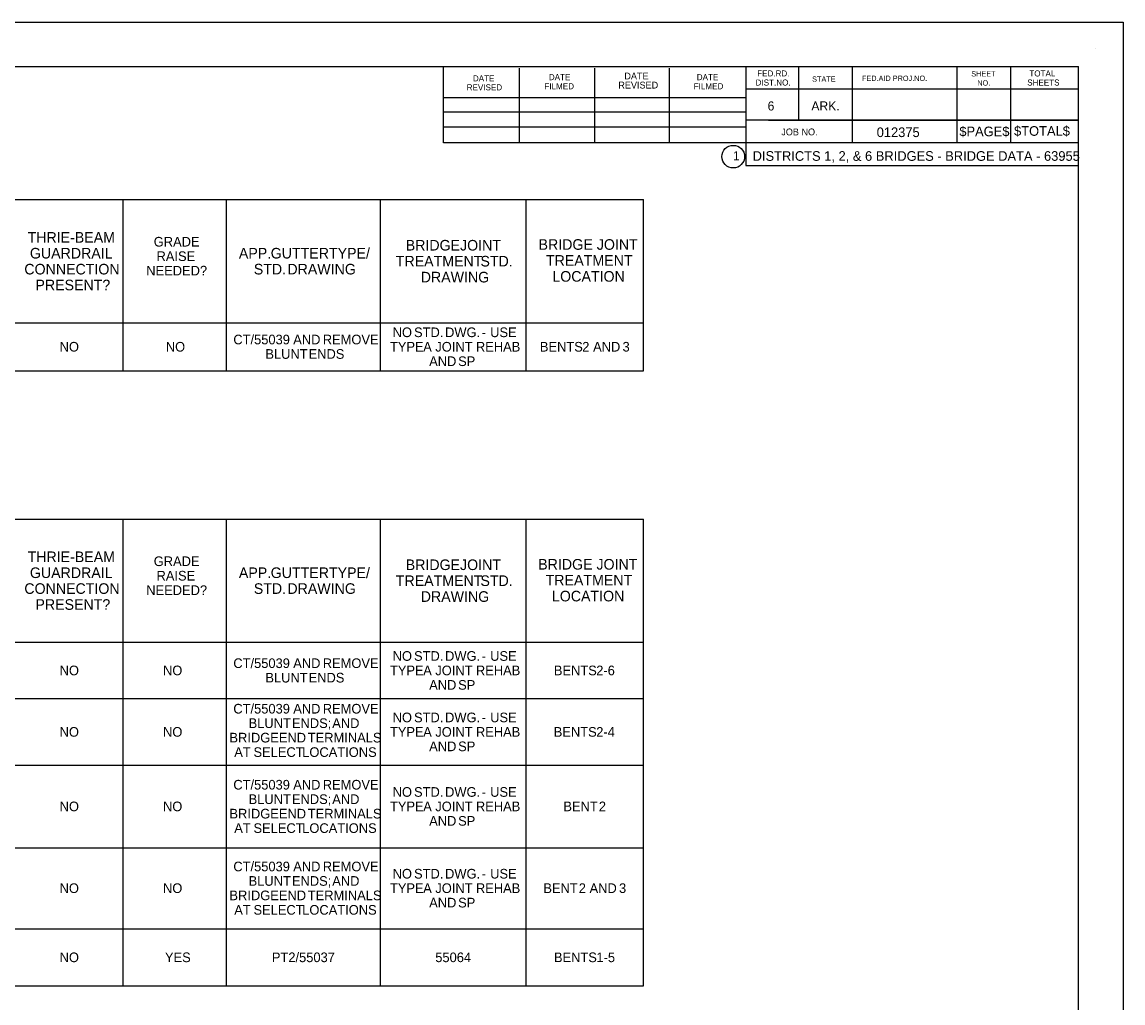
# Model space of a CAD drawing. Extents: x 16 to 1228740, y 11 to 152440.
# Drawn here: x 17.302 to 18.49, y 11.485 to 12.543 of the extents above; entities that cross this region are included whole.
import ezdxf

# ---------------------------------------------------------------- set-up
doc = ezdxf.new("R2010")
doc.units = 0
for name, color, linetype in [('B_Copy In', 7, 'Continuous'), ('B_Text', 7, 'Continuous'), ('R_Border', 7, 'Continuous')]:
    doc.layers.add(name, color=color, linetype=linetype)

msp = doc.modelspace()

# ---------------------------------------------------------------- linework, layer by layer
at = {"layer": 'B_Text'}
for p, q in [((16.2529, 12.3512), (17.9726, 12.3512)), ((17.4109, 12.1667), (17.4109, 12.3512)), ((17.5224, 12.1667), (17.5224, 12.3512)), ((17.6887, 12.1667), (17.6887, 12.3512)), ((17.8459, 12.1667), (17.8459, 12.3512)), ((17.9726, 12.1667), (17.9726, 12.3512)), ((16.2529, 12.2184), (17.9726, 12.2184)), ((16.2529, 12.2184), (17.9726, 12.2184)), ((16.2529, 12.1667), (17.9726, 12.1667)), ((16.2529, 12.0066), (17.9726, 12.0066)), ((17.4109, 11.5029), (17.4109, 12.0066)), ((17.5224, 11.5029), (17.5224, 12.0066)), ((17.6887, 11.5029), (17.6887, 12.0066)), ((17.8459, 11.5029), (17.8459, 12.0066)), ((17.9726, 11.5029), (17.9726, 12.0066)), ((16.2529, 11.8737), (17.9726, 11.8737)), ((16.2529, 11.8129), (17.9726, 11.8129)), ((16.2529, 11.7412), (17.9726, 11.7412)), ((16.2529, 11.652), (17.9726, 11.652)), ((16.2529, 11.5647), (17.9726, 11.5647)), ((16.2529, 11.5029), (17.9726, 11.5029))]:
    msp.add_line(p, q, dxfattribs=at)
at = {"layer": 'R_Border'}
for p, q in [((18.4604, 12.514), (18.4604, 12.514)), ((15.7833, 12.4948), (18.4422, 12.4948)), ((17.7567, 12.4124), (17.7567, 12.4948)), ((17.8389, 12.4124), (17.8389, 12.4931)), ((17.9202, 12.4124), (17.9202, 12.4931)), ((18.0009, 12.4124), (18.0009, 12.4931)), ((18.083, 12.4948), (18.083, 12.3881)), ((18.14, 12.4948), (18.14, 12.4369)), ((18.1979, 12.4948), (18.1979, 12.4124)), ((18.311, 12.4948), (18.311, 12.4124)), ((18.3689, 12.4948), (18.3689, 12.4124)), ((18.4422, 10.7576), (18.4422, 12.4948)), ((18.4422, 12.4703), (18.083, 12.4703)), ((18.4422, 12.4704), (18.4422, 12.4704)), ((17.7567, 12.4613), (18.083, 12.4613)), ((17.7567, 12.4458), (18.083, 12.4458)), ((18.4422, 12.4369), (18.083, 12.4369)), ((18.1077, 12.4369), (18.4422, 12.4369)), ((17.7567, 12.4124), (17.7567, 12.4296)), ((17.7567, 12.4296), (18.083, 12.4296)), ((18.4422, 12.4124), (17.7567, 12.4124)), ((18.083, 12.3881), (18.4422, 12.3881)), ((18.083, 12.3881), (18.4422, 12.3881))]:
    msp.add_line(p, q, dxfattribs=at)
msp.add_lwpolyline([(15.6569, 12.5428), (18.4903, 12.5428), (18.4903, 10.7095), (15.6569, 10.7095)], close=True, dxfattribs=at)
msp.add_circle((18.0696, 12.3976), 0.0122, dxfattribs=at)

# ---------------------------------------------------------------- texts
at = {"layer": 'B_Copy In'}
msp.add_text('DISTRICTS 1, 2, & 6 BRIDGES - BRIDGE DATA - 63955', height=0.0104, dxfattribs=at).set_placement((18.0905, 12.3931))
at = {"layer": 'B_Text'}
for s, height, p in [('THRIE-BEAM', 0.01144, (17.3078, 12.3048)), ('GRADE', 0.0104, (17.444, 12.3006)), ('BRIDGE', 0.01144, (17.716, 12.2963)), (' JOINT', 0.01144, (17.7704, 12.2963)), ('BRIDGE JOINT', 0.01144, (17.8594, 12.2971)), ('GUARDRAIL', 0.01144, (17.3103, 12.2877)), ('RAISE', 0.0104, (17.447, 12.285)), ('APP.', 0.01144, (17.5359, 12.2877)), (' GUTTER', 0.01144, (17.566, 12.2877)), (' TYPE/', 0.01144, (17.6289, 12.2877)), ('TREATMENT', 0.01144, (17.7053, 12.2791)), (' STD.', 0.01144, (17.7924, 12.2791)), ('TREATMENT', 0.01144, (17.8674, 12.2799)), ('CONNECTION', 0.01144, (17.3043, 12.2705)), ('NEEDED?', 0.0104, (17.4359, 12.2694)), ('STD.', 0.01144, (17.552, 12.2705)), (' DRAWING', 0.01144, (17.584, 12.2705)), ('DRAWING', 0.01144, (17.7322, 12.2619)), ('LOCATION', 0.01144, (17.8743, 12.2627)), ('PRESENT?', 0.01144, (17.3163, 12.2534)), ('CT/55039', 0.0104, (17.5299, 12.1951)), ('NO', 0.0104, (17.7019, 12.2029)), (' STD.', 0.0104, (17.7211, 12.2029)), (' DWG.', 0.0104, (17.7546, 12.2029)), (' -', 0.0104, (17.7942, 12.2029)), (' USE', 0.0104, (17.8033, 12.2029)), ('NO', 0.0104, (17.3424, 12.1873)), ('NO', 0.0104, (17.457, 12.1873)), (' AND', 0.0104, (17.5907, 12.1951)), (' REMOVE', 0.0104, (17.6226, 12.1951)), ('TYPE', 0.0104, (17.699, 12.1873)), (' A', 0.0104, (17.731, 12.1873)), (' JOINT', 0.0104, (17.7441, 12.1873)), (' REHAB', 0.0104, (17.7879, 12.1873)), ('BENTS', 0.0104, (17.8608, 12.1873)), (' 2', 0.0104, (17.9027, 12.1873)), (' AND', 0.0104, (17.9144, 12.1873)), (' 3', 0.0104, (17.9462, 12.1873)), ('BLUNT', 0.0104, (17.5645, 12.1795)), (' ENDS', 0.0104, (17.6073, 12.1795)), ('AND', 0.0104, (17.7413, 12.1717)), (' SP', 0.0104, (17.7687, 12.1717)), ('THRIE-BEAM', 0.01144, (17.3078, 11.9602)), ('GRADE', 0.0104, (17.444, 11.9559)), ('BRIDGE', 0.01144, (17.716, 11.9516)), (' JOINT', 0.01144, (17.7704, 11.9516)), ('BRIDGE JOINT', 0.01144, (17.859, 11.9521)), ('GUARDRAIL', 0.01144, (17.3103, 11.943)), ('RAISE', 0.0104, (17.447, 11.9403)), ('APP.', 0.01144, (17.5359, 11.943)), (' GUTTER', 0.01144, (17.566, 11.943)), (' TYPE/', 0.01144, (17.6289, 11.943)), ('TREATMENT', 0.01144, (17.7053, 11.9344)), (' STD.', 0.01144, (17.7924, 11.9344)), ('TREATMENT', 0.01144, (17.867, 11.935)), ('CONNECTION', 0.01144, (17.3043, 11.9259)), ('NEEDED?', 0.0104, (17.4359, 11.9247)), ('STD.', 0.01144, (17.552, 11.9259)), (' DRAWING', 0.01144, (17.584, 11.9259)), ('DRAWING', 0.01144, (17.7322, 11.9173)), ('LOCATION', 0.01144, (17.8738, 11.9178)), ('PRESENT?', 0.01144, (17.3163, 11.9087)), ('NO', 0.0104, (17.7019, 11.8537)), (' STD.', 0.0104, (17.7211, 11.8537)), (' DWG.', 0.0104, (17.7546, 11.8537)), (' USE', 0.0104, (17.8033, 11.8537)), ('CT/55039', 0.0104, (17.5299, 11.8459)), (' AND', 0.0104, (17.5907, 11.8459)), (' REMOVE', 0.0104, (17.6226, 11.8459)), (' -', 0.0104, (17.7942, 11.8537)), ('NO', 0.0104, (17.3424, 11.8381)), ('NO', 0.0104, (17.454, 11.8381)), ('BLUNT', 0.0104, (17.5645, 11.8303)), (' ENDS', 0.0104, (17.6073, 11.8303)), ('TYPE', 0.0104, (17.699, 11.8381)), (' A', 0.0104, (17.731, 11.8381)), (' JOINT', 0.0104, (17.7441, 11.8381)), (' REHAB', 0.0104, (17.7879, 11.8381)), ('BENTS', 0.0104, (17.8759, 11.8381)), (' 2-6', 0.0104, (17.9178, 11.8381)), ('AND', 0.0104, (17.7413, 11.8225)), (' SP', 0.0104, (17.7687, 11.8225)), ('CT/55039', 0.0104, (17.5299, 11.7968)), (' AND', 0.0104, (17.5907, 11.7968)), (' REMOVE', 0.0104, (17.6226, 11.7968)), ('BLUNT', 0.0104, (17.5464, 11.7812)), (' ENDS;', 0.0104, (17.5893, 11.7812)), (' AND', 0.0104, (17.6328, 11.7812)), ('NO', 0.0104, (17.7019, 11.7874)), (' STD.', 0.0104, (17.7211, 11.7874)), (' DWG.', 0.0104, (17.7546, 11.7874)), (' -', 0.0104, (17.7942, 11.7874)), (' USE', 0.0104, (17.8033, 11.7874)), ('NO', 0.0104, (17.3424, 11.7718)), ('NO', 0.0104, (17.454, 11.7718)), ('TYPE', 0.0104, (17.699, 11.7718)), (' A', 0.0104, (17.731, 11.7718)), (' JOINT', 0.0104, (17.7441, 11.7718)), (' REHAB', 0.0104, (17.7879, 11.7718)), ('BENTS', 0.0104, (17.8758, 11.7718)), (' 2-4', 0.0104, (17.9178, 11.7718)), ('BRIDGE', 0.0104, (17.5257, 11.7656)), (' END', 0.0104, (17.5752, 11.7656)), (' TERMINALS', 0.0104, (17.6064, 11.7656)), ('AND', 0.0104, (17.7413, 11.7562)), (' SP', 0.0104, (17.7687, 11.7562)), ('AT', 0.0104, (17.5309, 11.75)), (' SELECT', 0.0104, (17.5478, 11.75)), (' LOCATIONS', 0.0104, (17.6004, 11.75)), ('CT/55039', 0.0104, (17.5299, 11.7148)), (' AND', 0.0104, (17.5907, 11.7148)), (' REMOVE', 0.0104, (17.6226, 11.7148)), ('BLUNT', 0.0104, (17.5464, 11.6992)), (' ENDS;', 0.0104, (17.5893, 11.6992)), (' AND', 0.0104, (17.6328, 11.6992)), ('NO', 0.0104, (17.7019, 11.707)), (' STD.', 0.0104, (17.7211, 11.707)), (' DWG.', 0.0104, (17.7546, 11.707)), (' -', 0.0104, (17.7942, 11.707)), (' USE', 0.0104, (17.8033, 11.707)), ('NO', 0.0104, (17.3424, 11.6914)), ('NO', 0.0104, (17.454, 11.6914)), ('TYPE', 0.0104, (17.699, 11.6914)), (' A', 0.0104, (17.731, 11.6914)), (' JOINT', 0.0104, (17.7441, 11.6914)), (' REHAB', 0.0104, (17.7879, 11.6914)), ('BENT', 0.0104, (17.8862, 11.6914)), (' 2', 0.0104, (17.9206, 11.6914)), ('BRIDGE', 0.0104, (17.5257, 11.6836)), (' END', 0.0104, (17.5752, 11.6836)), (' TERMINALS', 0.0104, (17.6064, 11.6836)), ('AND', 0.0104, (17.7413, 11.6758)), (' SP', 0.0104, (17.7687, 11.6758)), ('AT', 0.0104, (17.5309, 11.668)), (' SELECT', 0.0104, (17.5478, 11.668)), (' LOCATIONS', 0.0104, (17.6004, 11.668)), ('CT/55039', 0.0104, (17.5299, 11.6266)), (' AND', 0.0104, (17.5907, 11.6266)), (' REMOVE', 0.0104, (17.6226, 11.6266)), ('NO', 0.0104, (17.7019, 11.6188)), (' STD.', 0.0104, (17.7211, 11.6188)), (' DWG.', 0.0104, (17.7546, 11.6188)), (' -', 0.0104, (17.7942, 11.6188)), (' USE', 0.0104, (17.8033, 11.6188)), ('NO', 0.0104, (17.3424, 11.6032)), ('NO', 0.0104, (17.454, 11.6032)), ('BLUNT', 0.0104, (17.5464, 11.611)), (' ENDS;', 0.0104, (17.5893, 11.611)), (' AND', 0.0104, (17.6328, 11.611)), ('TYPE', 0.0104, (17.699, 11.6032)), (' A', 0.0104, (17.731, 11.6032)), (' JOINT', 0.0104, (17.7441, 11.6032)), (' REHAB', 0.0104, (17.7879, 11.6032)), ('BENT', 0.0104, (17.8646, 11.6032)), (' 2', 0.0104, (17.8989, 11.6032)), (' AND', 0.0104, (17.9106, 11.6032)), (' 3', 0.0104, (17.9424, 11.6032)), ('BRIDGE', 0.0104, (17.5257, 11.5954)), (' END', 0.0104, (17.5752, 11.5954)), (' TERMINALS', 0.0104, (17.6064, 11.5954)), ('AT', 0.0104, (17.5309, 11.5798)), (' SELECT', 0.0104, (17.5478, 11.5798)), (' LOCATIONS', 0.0104, (17.6004, 11.5798)), ('AND', 0.0104, (17.7413, 11.5876)), (' SP', 0.0104, (17.7687, 11.5876)), ('NO', 0.0104, (17.3424, 11.5286)), ('YES', 0.0104, (17.4561, 11.5286)), ('PT2/55037', 0.0104, (17.5715, 11.5286)), ('55064', 0.0104, (17.7479, 11.5286)), ('BENTS', 0.0104, (17.876, 11.5286)), (' 1-5', 0.0104, (17.918, 11.5286))]:
    msp.add_text(s, height=height, dxfattribs=at).set_placement(p)
at = {"layer": 'R_Border'}
for s, height, p in [('DATE', 0.00652, (17.7885, 12.4788)), ('DATE', 0.00652, (17.8705, 12.4801)), ('DATE', 0.00733, (17.952, 12.4809)), ('DATE', 0.00652, (18.0302, 12.4801)), ('DIST.NO.', 0.00652, (18.0937, 12.4743)), ('FED.RD.', 0.00652, (18.0954, 12.4841)), ('STATE', 0.0057, (18.1547, 12.4784)), ('FED.AID PROJ.NO.', 0.0057, (18.2085, 12.4793)), ('SHEET', 0.0057, (18.3265, 12.4841)), ('NO.', 0.0057, (18.333, 12.4743)), ('SHEETS', 0.00652, (18.3869, 12.4743)), ('TOTAL', 0.00652, (18.3892, 12.4841)), ('REVISED', 0.00652, (17.7818, 12.4691)), ('FILMED', 0.00652, (17.8657, 12.4703)), ('REVISED', 0.00733, (17.9455, 12.4711)), ('FILMED', 0.00652, (18.0269, 12.4703)), ('6', 0.00977, (18.1067, 12.4474)), ('ARK.', 0.00977, (18.1539, 12.4474)), ('JOB NO.', 0.00733, (18.1214, 12.4206)), ('012375', 0.0104, (18.2244, 12.4187)), ('$PAGE$', 0.0104, (18.3136, 12.4196)), ('$TOTAL$', 0.0104, (18.3727, 12.4201)), ('1', 0.00977, (18.0693, 12.3937))]:
    msp.add_text(s, height=height, dxfattribs=at).set_placement(p)

doc.saveas('drawing.dxf')
